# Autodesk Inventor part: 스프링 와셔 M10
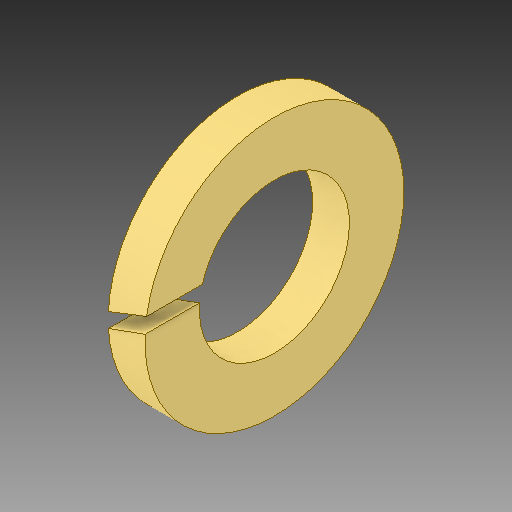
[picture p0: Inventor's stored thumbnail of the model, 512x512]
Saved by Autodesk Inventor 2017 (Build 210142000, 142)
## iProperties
Created: 2024-08
Part Number: 스프링 와셔 M10
Material: 일반
Description: 스프링 잠금 와셔
Document SubType Name: Modeling
Designer: MRC
Density: 1 g/cm^3
Appearance: 기본값
Author: jhkim
Sending System: Autodesk Inventor 2025
Preprocessor: ST-DEVELOPER v20
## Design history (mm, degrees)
feature "Solid1"
node "솔리드1"
